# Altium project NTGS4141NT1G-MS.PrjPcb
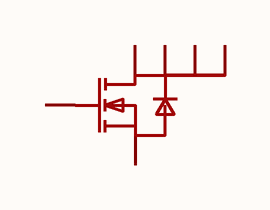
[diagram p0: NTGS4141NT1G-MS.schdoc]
1 sheet, 1 parts. Net scope: global (net labels, ports and power ports of the same name join across sheets).

## Sheet NTGS4141NT1G-MS.schdoc
size 127 x 101 mm

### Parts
Q?  ntgs4141nt1g-ms  [TSOP-6_L3.1-W1.7-P0.95-LS2.9-BL]  (value not drawn)

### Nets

Not connected (* = marked no-connect by the designer): Q? 1(D) 2(D) 3(S) 4(G) 5(D) 6(D)

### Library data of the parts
Q? = ntgs4141nt1g-ms: 数量:1个N沟道;漏源电压(Vdss):30V;连续漏极电流(Id):6A;导通电阻(RDS(on)):18mΩ@10V;耗散功率(Pd):1.4W;阈值电压(Vgs(th)):1.6V;; Manufacturer: MSKSEMI(美森科); AddInBom: yes; ModelId: 8cfb63cd4bc84e90b1efc846220e4314; ModelTransform: 120.0785,114.173,0,0,0,0,0,0,0; Number: 1个N沟道; Drain to Source Voltage: 30V; Current - Continuous Drain(Id): 6A; Pd - Power Dissipation: 1.4W; Gate Threshold Voltage (Vgs(th)): 1.6V; Gate Charge(Qg): 4.1nC; Input Capacitance(Ciss): 345pF; Reverse Transfer Capacitance (Crss@Vds): 32pF; Configuration: 独立式; Type: N沟道; Output Capacitance(Coss): 55pF; Vgs: ±20V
